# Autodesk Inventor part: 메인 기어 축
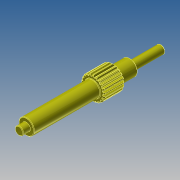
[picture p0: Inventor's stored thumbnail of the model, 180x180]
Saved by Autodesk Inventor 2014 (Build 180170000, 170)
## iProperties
Created: 2018-12
Part Number: 메인 기어 축
Material: 강철, 연강
Document SubType Name: Modeling
Designer: mduedu
Categories: <?xml version="1.0" encoding="UTF-16"?> <MemberInstance><Categories><FamilyTemplate><FamilyTemplateParameter ValueType="xs:double" Id="1" ObjectReferenceKey="da
Density: 7.86 g/cm^3
Appearance: 노란색
Mass: 179.676 g
Surface Area: 75.4119 cm^2
Volume: 22.8595 cm^3
Author: mduedu
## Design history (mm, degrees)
sketch "Sketch1"
  geometry: C1 r 11.3 at (0, 0)
  constraints: 1 centre point
  dimensions: "d0" = 22.6 diameter of C1 (= da_da)
extrude "Extrusion1" new body sketch "Sketch1" distance "d1" = 20 (= da_b); taper "d2" = 0 deg
workplane "Work Plane2"
sketch "Sketch2"
  geometry: C1 r 11.3 at (0, 0) reference; C2 r 10.5 at (0, 0)
  constraints: 1 centre point, 1 coincident
  dimensions: "d3" = 21 diameter of C2 (= da_dw)
feature "피치 지름" sketch "Sketch2" dims "d4" = 10, "d5" = 0
workplane "Work Plane8"
workplane "Work Plane9"
chamfer "모따기1" distance "d49" = 1; stored, may be unused: second distance "d50" = 2, angle "d51" = 45 deg
sketch "스케치3"
  geometry: C1 r 7.5 at (0, 0); 1 further point
  constraints: 1 centre point, 1 coincident
  dimensions: "d52" = 15 diameter of C1
extrude "돌출2" join sketch "스케치3" distance "d53" = 64; taper "d54" = 0 deg
sketch "스케치4"
  geometry: C1 r 4 at (0, 0); 1 further point
  constraints: 1 centre point, 1 coincident
  dimensions: "d55" = 8 diameter of C1
extrude "돌출3" join sketch "스케치4" distance "d56" = 7; taper "d57" = 0 deg
sketch "스케치5"
  geometry: C1 r 7.5 at (0, 0) reference; C2 r 7.5 at (0, 0) reference; 1 further point
extrude "돌출4" join sketch "스케치5" distance "d58" = 16; taper "d59" = 0 deg
sketch "스케치6"
  geometry: C1 r 4 at (0, 0); 1 further point
  constraints: 1 centre point, 1 coincident
  dimensions: "d60" = 8 diameter of C1
extrude "돌출5" join sketch "스케치6" distance "d61" = 30; taper "d62" = 0 deg
chamfer "모따기2" distance "d63" = 0.5; stored, may be unused: second distance "d64" = 2, angle "d65" = 45 deg
fillet "모깎기1" dims "d66" = 0.5
feature "스퍼 기어" dims "da_b" = 20, "da_d" = 21, "da_aw" = 31, "da_da" = 22.6, "da_df" = 19.086, "da_dw" = 21, angle "da_beta" = 0 deg, "da_lefttooth" = 0, "da_righttooth" = 0
sketch "스케치7" dims "d67" = 18
  geometry: C1 r 0.25 at (0, -9); 2 further points
  constraints: 2 vertical alignment, 1 centre point, 1 coincident, 2 other
  dimensions: "d68" = 0.5 diameter of C1
extrude "돌출6" join sketch "스케치7" distance "d69" = 0.3; taper "d70" = 0 deg
body "Solid1"
body "Srf1"
node "투영된 루프1"
other parameters: "d16" = 31 (= da_aw), "d17" = 0, "d34" = 1.496 (computed from da_z), "d39" = 0, "d41" = 0, "d43" = 31 (= da_aw), "d46" = 31 (= da_aw), "d47" = 0, "d48" = 0
